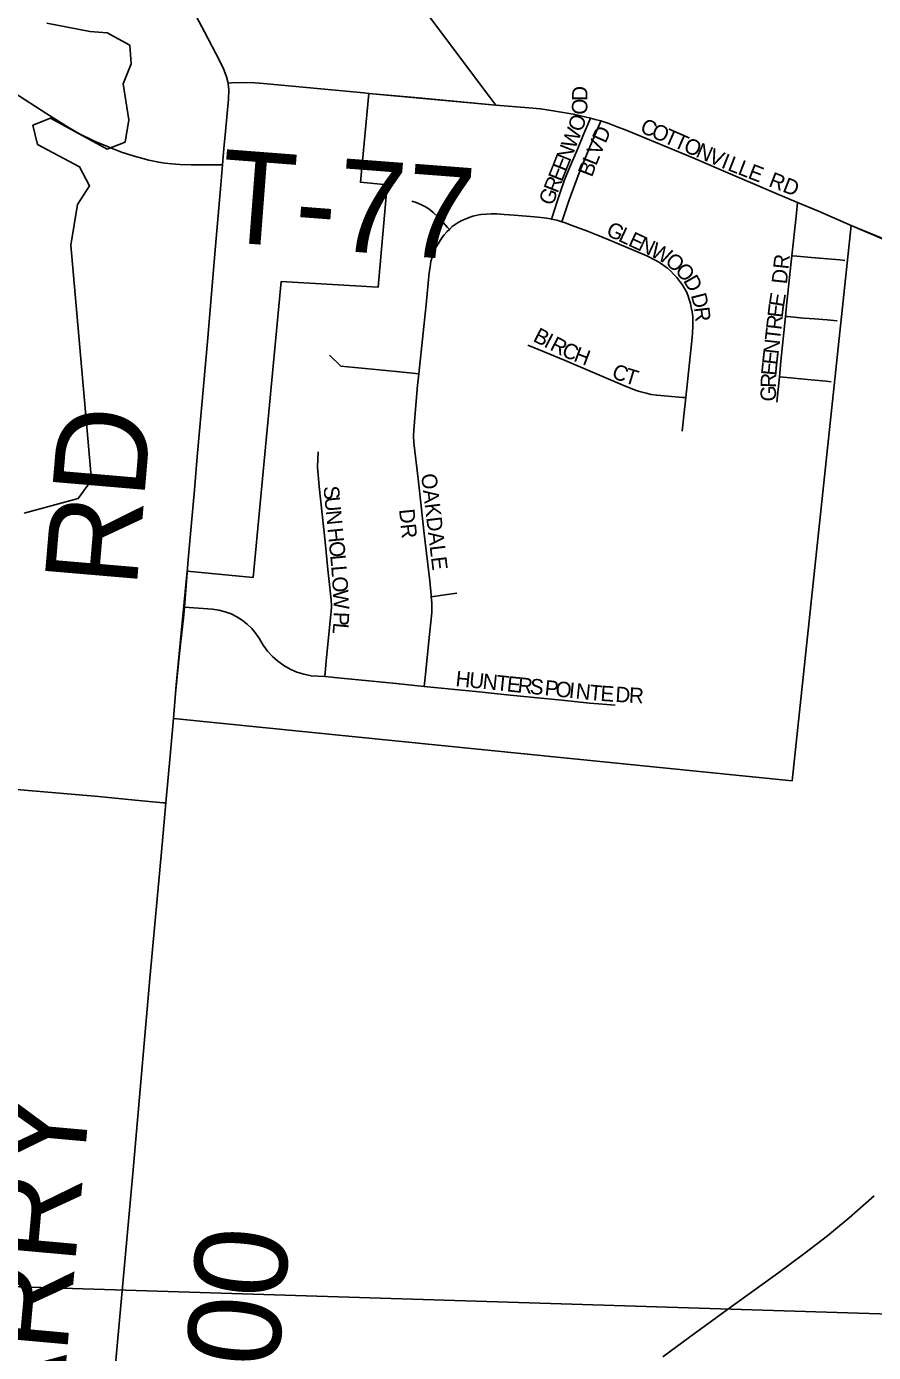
# Model space of a CAD drawing. Extents: x -5.4 to 49.9, y 13.2 to 48.4.
# Drawn here: x 27.924 to 28.445, y 42.711 to 43.526 of the extents above; entities that cross this region are included whole.
import ezdxf

# ---------------------------------------------------------------- set-up
doc = ezdxf.new("R2010")
doc.units = 0
for name, color, linetype in [('GM_X_City_Street', 7, 'Continuous'), ('GM_X_City_Street_Text', 7, 'Continuous'), ('GM_X_Corporation', 7, 'Continuous'), ('GM_X_County_Road', 7, 'Continuous'), ('GM_X_County_Road_Text', 7, 'Continuous'), ('GM_X_Major_Lake', 7, 'Continuous'), ('GM_X_Township_Road', 7, 'Continuous'), ('GM_X_Township_Road_Text', 7, 'Continuous')]:
    doc.layers.add(name, color=color, linetype=linetype)

msp = doc.modelspace()

# ---------------------------------------------------------------- linework, layer by layer
at = {"layer": 'GM_X_City_Street'}
for points in [[(28.21277, 43.47818), (28.2332, 43.47653), (28.24022, 43.4758), (28.24811, 43.47469), (28.26034, 43.47252)], [(28.24705, 43.40809), (28.2474, 43.40916), (28.25033, 43.41815), (28.25254, 43.42503), (28.25497, 43.43214), (28.25816, 43.4396), (28.26315, 43.45143), (28.26676, 43.45996), (28.2706, 43.469), (28.27104, 43.47007)], [(28.25347, 43.40637), (28.25368, 43.407), (28.25778, 43.41921), (28.26408, 43.43648), (28.26735, 43.44453), (28.27185, 43.45533), (28.27668, 43.4669), (28.27728, 43.46835)], [(28.26034, 43.47252), (28.26046, 43.4725), (28.27104, 43.47007)], [(28.27104, 43.47007), (28.27384, 43.4693), (28.27728, 43.46835)], [(28.27728, 43.46835), (28.28231, 43.46684), (28.28732, 43.46486), (28.29292, 43.46275), (28.3345, 43.44546), (28.34958, 43.43886), (28.38516, 43.42376), (28.39824, 43.41828)], [(28.18426, 43.40173), (28.18316, 43.40289), (28.17902, 43.40758), (28.17721, 43.40949), (28.17439, 43.41209), (28.17264, 43.41358), (28.17101, 43.41476), (28.16918, 43.41581), (28.16721, 43.41674), (28.16396, 43.41816), (28.16115, 43.41901)], [(28.39471, 43.38548), (28.39731, 43.4096), (28.39824, 43.41828)], [(28.39824, 43.41828), (28.41104, 43.41291), (28.43126, 43.40403)], [(28.18426, 43.40173), (28.18605, 43.4034), (28.18779, 43.40469), (28.18964, 43.40588), (28.19201, 43.40719), (28.19406, 43.40808), (28.19645, 43.40896), (28.19878, 43.40977), (28.20138, 43.4104), (28.20365, 43.41079), (28.20709, 43.41112), (28.20986, 43.4112), (28.21353, 43.41124), (28.21802, 43.41096), (28.22408, 43.41056), (28.23656, 43.40944), (28.24252, 43.40884), (28.24664, 43.40818), (28.24705, 43.40809)], [(28.16541, 43.3129), (28.16998, 43.3556), (28.17188, 43.37524), (28.17238, 43.37868), (28.17292, 43.38201), (28.17365, 43.38462), (28.17432, 43.38678), (28.1752, 43.38883), (28.1764, 43.3913), (28.17792, 43.39382), (28.17971, 43.39658), (28.18114, 43.39837), (28.18286, 43.40044), (28.18426, 43.40173)], [(28.24705, 43.40809), (28.25033, 43.40732), (28.25347, 43.40637)], [(28.32956, 43.29833), (28.33345, 43.33519), (28.33368, 43.33817), (28.33387, 43.34195), (28.33392, 43.34518), (28.33381, 43.34823), (28.33338, 43.35097), (28.33289, 43.35365), (28.33235, 43.35609), (28.33168, 43.35857), (28.33076, 43.36121), (28.32991, 43.36328), (28.32875, 43.36541), (28.32735, 43.36779), (28.32584, 43.36974), (28.32412, 43.37206), (28.32229, 43.37407), (28.32016, 43.37626), (28.31827, 43.37791), (28.31542, 43.38002), (28.31346, 43.38132), (28.31121, 43.38268), (28.30561, 43.38538), (28.28481, 43.39425), (28.27635, 43.39776), (28.26922, 43.40059), (28.2591, 43.40439), (28.25538, 43.40581), (28.25347, 43.40637)], [(28.39081, 43.34821), (28.39149, 43.35473), (28.39413, 43.38001), (28.39471, 43.38548)], [(28.39471, 43.38548), (28.39549, 43.38541), (28.40911, 43.38423), (28.42421, 43.38291), (28.42733, 43.38265)], [(28.38707, 43.31119), (28.38798, 43.32081), (28.39081, 43.34821)], [(28.39081, 43.34821), (28.39201, 43.3481), (28.40213, 43.34725), (28.40855, 43.3467), (28.41642, 43.34604), (28.42261, 43.34543)], [(28.23242, 43.3306), (28.24245, 43.3265), (28.25547, 43.32117), (28.29041, 43.30619), (28.29909, 43.30278), (28.3019, 43.30182), (28.30511, 43.30096), (28.30831, 43.30022), (28.3118, 43.29983), (28.32755, 43.29849), (28.32956, 43.29833)], [(28.11072, 43.32445), (28.11767, 43.31759), (28.12627, 43.31676), (28.14323, 43.31509), (28.15567, 43.31386), (28.16541, 43.3129)], [(28.17319, 43.17593), (28.17308, 43.17694), (28.17219, 43.1856), (28.17082, 43.19764), (28.16888, 43.21457), (28.16695, 43.23151), (28.16501, 43.24845), (28.16249, 43.27046), (28.16225, 43.27476), (28.16239, 43.27803), (28.16332, 43.28882), (28.16479, 43.30574), (28.16541, 43.3129)], [(28.38552, 43.29552), (28.3867, 43.30724), (28.38707, 43.31119)], [(28.38707, 43.31119), (28.39391, 43.31053), (28.40431, 43.30951), (28.41572, 43.3084), (28.41882, 43.30799)], [(28.32738, 43.27763), (28.3286, 43.28927), (28.32956, 43.29833)], [(28.10773, 43.12693), (28.10867, 43.13637), (28.11153, 43.16515), (28.11166, 43.16644), (28.11186, 43.17024), (28.11165, 43.17405), (28.10969, 43.19269), (28.1079, 43.20968), (28.10611, 43.22663), (28.10433, 43.24358), (28.10356, 43.25093), (28.10336, 43.25315), (28.1033, 43.25538), (28.1033, 43.25573), (28.10363, 43.26494)], [(28.16887, 43.12079), (28.16982, 43.13021), (28.17169, 43.14887), (28.17344, 43.16626), (28.17359, 43.16829), (28.17349, 43.17211), (28.17319, 43.17593)], [(28.17319, 43.17593), (28.18291, 43.1773), (28.18895, 43.17814)], [(28.02143, 43.16948), (28.03869, 43.16819), (28.04259, 43.16766), (28.04641, 43.16673), (28.05012, 43.16539), (28.05365, 43.16367), (28.05699, 43.16158), (28.06008, 43.15915), (28.0629, 43.15641), (28.06542, 43.15338), (28.0676, 43.1501), (28.06985, 43.1462), (28.0725, 43.14255), (28.07552, 43.13922), (28.07888, 43.13622), (28.08255, 43.13359), (28.08647, 43.13137), (28.0906, 43.12958), (28.0949, 43.12824), (28.09933, 43.12736), (28.10773, 43.12693)], [(28.10773, 43.12693), (28.11776, 43.12593), (28.13472, 43.12422), (28.15168, 43.12252), (28.16887, 43.12079)], [(28.16887, 43.12079), (28.1856, 43.1191), (28.20256, 43.1174), (28.21953, 43.11569), (28.23648, 43.11399), (28.25345, 43.11228), (28.2704, 43.11058), (28.2759, 43.11003), (28.28609, 43.10921)]]:
    msp.add_lwpolyline(points, dxfattribs=at)
at = {"layer": 'GM_X_Corporation'}
for points in [[(28.49347, 43.37841), (28.43126, 43.40403), (28.39493, 43.06284), (28.01471, 43.10114), (28.01642, 43.12177), (28.02321, 43.19167), (28.06371, 43.18776), (28.08095, 43.36972), (28.14049, 43.36615), (28.14607, 43.42915), (28.12965, 43.43068), (28.13476, 43.48525), (28.21277, 43.47818), (28.2091, 43.48293), (28.10396, 43.6235), (28.26522, 43.76952), (28.25919, 43.77635), (28.43166, 43.73848), (28.47498, 43.72897)], [(28.56624, 42.73136), (27.6459, 42.76038), (27.65346, 42.77968), (27.66125, 42.80482), (27.66239, 42.8295), (27.65632, 42.86559), (27.64493, 42.90851), (27.63544, 42.95751), (27.63165, 43.0084), (27.62938, 43.07411), (27.63204, 43.1212), (27.63225, 43.22236), (27.63841, 43.24417), (27.64404, 43.26266), (27.64805, 43.28356), (27.65287, 43.30045), (27.65294, 43.33325), (27.64345, 43.4163), (27.62902, 43.46569), (27.607, 43.51963), (27.59725, 43.55802)]]:
    msp.add_lwpolyline(points, dxfattribs=at)
at = {"layer": 'GM_X_County_Road'}
for points in [[(28.04829, 43.4917), (28.04733, 43.49559), (28.04527, 43.50095), (28.0407, 43.50988), (28.03385, 43.52313), (28.02197, 43.54567), (28.00878, 43.57101), (28.00234, 43.5844), (27.99822, 43.59407), (27.99427, 43.60511), (27.9904, 43.61816), (27.98754, 43.6302), (27.98548, 43.64177), (27.9839, 43.65468), (27.98303, 43.66702), (27.98293, 43.67877), (27.9837, 43.69298), (27.98381, 43.6938)], [(28.0449, 43.44142), (28.04578, 43.45135), (28.04672, 43.46193), (28.04855, 43.48176), (28.04877, 43.48747), (28.04839, 43.49127), (28.04829, 43.4917)], [(28.02143, 43.16948), (28.02376, 43.19888), (28.02762, 43.24158), (28.0294, 43.26201), (28.03322, 43.30534), (28.03579, 43.33504), (28.03876, 43.3697), (28.04059, 43.39136), (28.04381, 43.42914), (28.0449, 43.44142)], [(28.01471, 43.10113), (28.0159, 43.11651), (28.01753, 43.13314), (28.01906, 43.14671), (28.02083, 43.16273), (28.02143, 43.16948)], [(28.01008, 43.04914), (28.01271, 43.07804), (28.01471, 43.10113)], [(27.9506, 42.38475), (27.95084, 42.38785), (27.95474, 42.43699), (27.95734, 42.46545), (27.96325, 42.5298), (27.96646, 42.5638), (27.96988, 42.60218), (27.97483, 42.65735), (27.97843, 42.69747), (27.98429, 42.76057), (27.98999, 42.82369), (28.00032, 42.94129), (28.00775, 43.02359), (28.01008, 43.04914)], [(28.31543, 42.70862), (28.33186, 42.72084), (28.35748, 42.73949), (28.38667, 42.76062), (28.4027, 42.77242), (28.41654, 42.78299), (28.42041, 42.78613), (28.42998, 42.79408), (28.4454, 42.80764)]]:
    msp.add_lwpolyline(points, dxfattribs=at)
at = {"layer": 'GM_X_Major_Lake'}
for points in [[(27.95176, 43.39203), (27.95573, 43.41699), (27.96319, 43.42858), (27.957, 43.44011), (27.93115, 43.45395), (27.92838, 43.46578), (27.9391, 43.4701), (27.97393, 43.45112), (27.98502, 43.45543), (27.98722, 43.46904), (27.98392, 43.49112), (27.98874, 43.50354), (27.98786, 43.51494), (27.974, 43.52245), (27.96341, 43.52345), (27.93699, 43.52858)], [(27.92306, 43.22721), (27.95625, 43.23635), (27.96446, 43.24755), (27.95176, 43.39203)]]:
    msp.add_lwpolyline(points, dxfattribs=at)
at = {"layer": 'GM_X_Township_Road'}
for points in [[(28.04829, 43.4917), (28.05041, 43.49182), (28.05954, 43.49206), (28.06464, 43.49182), (28.07, 43.49144), (28.13173, 43.48556), (28.13476, 43.48525)], [(27.91666, 43.48587), (27.93699, 43.47281), (27.94957, 43.46475), (27.95662, 43.46073), (27.96612, 43.456), (27.97763, 43.45118), (27.98291, 43.44926), (27.99, 43.44691), (27.9996, 43.4442), (28.0057, 43.44296), (28.0094, 43.4424), (28.01373, 43.44193), (28.0187, 43.44156), (28.02554, 43.44135), (28.04152, 43.4414), (28.0449, 43.44142)], [(28.13476, 43.48525), (28.16526, 43.48257), (28.19994, 43.47933), (28.21277, 43.47818)], [(28.43126, 43.40403), (28.45092, 43.39565)], [(27.88335, 43.06095), (27.89044, 43.06024), (27.91351, 43.05792), (27.96863, 43.05303), (27.98907, 43.05107), (28.00831, 43.0493), (28.01008, 43.04914)]]:
    msp.add_lwpolyline(points, dxfattribs=at)

# ---------------------------------------------------------------- texts
at = {"layer": 'GM_X_City_Street_Text'}
for s, rotation, p in [('D', 90.01537, (28.26914, 43.48072)), ('O', 88.6303, (28.26894, 43.47214)), ('O', 70.87342, (28.26564, 43.46113)), ('C', 336.22739, (28.30081, 43.46175)), ('O', 336.2217, (28.30767, 43.45872)), ('W', 68.28288, (28.26147, 43.45062)), ('D', 65.85995, (28.28021, 43.45413)), ('T', 336.25718, (28.3153, 43.45536)), ('T', 336.2345, (28.32141, 43.45267)), ('N', 68.30296, (28.25839, 43.44288)), ('V', 66.78992, (28.27694, 43.44651)), ('O', 336.22877, (28.32751, 43.44999)), ('N', 336.2217, (28.33513, 43.44663)), ('V', 336.72839, (28.34284, 43.44323)), ('E', 68.27977, (28.25592, 43.43668)), ('B', 69.29899, (28.27184, 43.43341)), ('L', 68.08192, (28.27447, 43.44038)), ('I', 338.25623, (28.35075, 43.43983)), ('L', 338.79287, (28.35471, 43.43825)), ('L', 338.82631, (28.36093, 43.43584)), ('E', 338.84885, (28.36715, 43.43343)), ('R', 68.29659, (28.25068, 43.42352)), ('E', 68.27977, (28.25346, 43.43049)), ('RD', 338.75126, (28.3799, 43.42844)), ('G', 68.28786, (28.2476, 43.41578)), ('G', 334.90125, (28.27999, 43.3984)), ('L', 334.88903, (28.28754, 43.39487)), ('E', 334.87873, (28.29357, 43.39204)), ('N', 334.8864, (28.29961, 43.38921)), ('W', 332.22423, (28.30705, 43.38573)), ('O', 321.1627, (28.31623, 43.38094)), ('DR', 83.99458, (28.39165, 43.3678)), ('O', 312.17078, (28.32244, 43.37599)), ('D', 299.75302, (28.32772, 43.37025)), ('D', 284.13168, (28.33259, 43.36135)), ('E', 81.08559, (28.38985, 43.35363)), ('R', 276.59494, (28.33456, 43.35359)), ('E', 83.20714, (28.38907, 43.3471)), ('R', 83.50156, (28.38823, 43.33967)), ('B', 332.62037, (28.23508, 43.33336)), ('I', 332.61398, (28.24174, 43.32991)), ('T', 83.51028, (28.38747, 43.33304)), ('R', 332.58763, (28.24544, 43.328)), ('C', 335.99508, (28.25265, 43.32428)), ('H', 339.35703, (28.26006, 43.321)), ('N', 83.4957, (28.38653, 43.32476)), ('E', 84.66457, (28.38517, 43.31155)), ('E', 83.59342, (28.38578, 43.31814)), ('C', 337.59873, (28.28337, 43.31088)), ('T', 343.06388, (28.29124, 43.30769)), ('R', 88.56729, (28.38499, 43.30422)), ('G', 89.86883, (28.38497, 43.29594)), ('OAKDALE', 276.81367, (28.16686, 43.25113)), ('S', 275.61001, (28.10687, 43.24362)), ('U', 275.60404, (28.10752, 43.23699)), ('N', 275.6198, (28.10833, 43.2287)), ('DR', 275.70736, (28.15333, 43.22952)), ('H', 275.60404, (28.10939, 43.21791)), ('O', 275.60719, (28.11021, 43.20962)), ('L', 275.44423, (28.11102, 43.20133)), ('L', 274.26668, (28.11165, 43.19475)), ('O', 273.45502, (28.11214, 43.18813)), ('W', 273.34771, (28.11264, 43.17982)), ('P', 267.62201, (28.11332, 43.16676)), ('L', 264.7734, (28.11306, 43.16022)), ('H', 354.08711, (28.18777, 43.12106)), ('U', 354.07857, (28.19606, 43.1202)), ('N', 354.07857, (28.20435, 43.11934)), ('T', 354.06106, (28.21263, 43.11848)), ('E', 354.08463, (28.21927, 43.11779)), ('R', 354.08886, (28.2259, 43.11711)), ('S', 354.08824, (28.23336, 43.11633)), ('P', 354.08463, (28.24248, 43.11539)), ('O', 354.09061, (28.24911, 43.1147)), ('I', 354.08936, (28.2574, 43.11384)), ('N', 354.08711, (28.26154, 43.11341)), ('T', 354.64432, (28.26993, 43.11254)), ('E', 356.21628, (28.27685, 43.1119)), ('D', 356.62645, (28.28607, 43.1113)), ('R', 356.62899, (28.29439, 43.11082))]:
    msp.add_text(s, height=0.00947, rotation=rotation, dxfattribs=at).set_placement(p)
at = {"layer": 'GM_X_County_Road_Text'}
for s, rotation, p in [('RD', 85.11466, (27.99203, 43.18076)), ('QUARRY', 84.81718, (27.93436, 42.54617)), ('C-100', 84.78049, (28.06762, 42.5793))]:
    msp.add_text(s, height=0.056818, rotation=rotation, dxfattribs=at).set_placement(p)
at = {"layer": 'GM_X_Township_Road_Text'}
msp.add_text('T-77', height=0.056818, rotation=355.60228, dxfattribs=at).set_placement((28.04158, 43.39442))

doc.saveas('drawing.dxf')
